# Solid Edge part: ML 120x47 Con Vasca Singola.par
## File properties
Title: ML 120 x 47 VASCA CENTRALE
Author: DESYS
Template: Iso Part.par
Last saved by: i.fialdini
Revision: 64
Application: Solid Edge
Tipo di contenuto documento: 0
Accuracy: 0.990
Document Number: 3007
Revision: 0
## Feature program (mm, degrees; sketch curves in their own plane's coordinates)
sketch for "unnamed Protrusion 1" plane through (10.8674, 0, 10.8674) normal (0, -1, 0) x-axis (1, 0, 0)
  line (-615.8674, 149.1326) -> (594.1326, 149.1326)
  line (594.1326, 149.1326) -> (594.1326, 94.1326)
  line (594.1326, 94.1326) -> (544.1326, 94.1326)
  arc centre (463.3203, 133.7479) radius 90 from (471.6326, 44.1326) to (544.1326, 94.1326) ccw
  line (454.1326, -10.8674) -> (471.6326, 44.1326)
  line (454.1326, -10.8674) -> (-475.8674, -10.8674)
  line (-475.8674, -10.8674) -> (-493.3674, 44.1326)
  arc centre (-485.0551, 133.7479) radius 90 from (-493.3674, 44.1326) to (-565.8674, 94.1326) cw
  line (-615.8674, 94.1326) -> (-565.8674, 94.1326)
  line (-615.8674, 149.1326) -> (-615.8674, 94.1326)
  dimension (linear) = 615.8674
  dimension (linear) = 615.8674
  dimension (linear) = 594.1326
  dimension (linear) = 454.1326
  dimension (linear) = 594.1326
  dimension (linear) = 615.8674
extrude "unnamed Protrusion 1" add finite 465 along +normal
sketch for "ScavoEstrusione_2" plane through (480, -232.5, 160) normal (0, 0, 1) x-axis (1, 0, 0)
  line (-1065, 212.5) -> (105, 212.5)
  line (105, 212.5) -> (105, -212.0497)
  line (105, -212.0497) -> (-1065, -212.0497)
  line (-1065, -212.0497) -> (-1065, 212.5)
  dimension (linear) = 105
  dimension (linear) = 1065
extrude "ScavoEstrusione_2" cut finite 12 along -normal
sketch for "ScavoEstrusione_12" plane through (0, -232.2749, 148) normal (0, 0, 1) x-axis (1, 0, 0)
  line (-315, -212.2749) -> (315, -212.2749)
  line (315, -212.2749) -> (315, 92.2749)
  line (315, 92.2749) -> (-315, 92.2749)
  line (-315, 92.2749) -> (-315, -212.2749)
  dimension (linear) = 315
extrude "ScavoEstrusione_12" cut finite 115 along -normal
fillet "Rotondo_1" radius 300
draft "Spoglia_8"  Angles1 = 5 deg
sketch for "unnamed Protrusion 2" plane through (0, 0, 0) normal (1, 0, 0) x-axis (0, 1, 0)
  line (-444.5497, 148) -> (-275, 33)
extrude "unnamed Protrusion 2" add through
sketch for "unnamed Cutout 1" plane through (0, 0, 0) normal (1, 0, 0) x-axis (0, 1, 0)
  line (-465, 105) -> (-410, 105)
  line (-410, 105) -> (-335, 55)
  line (-335, 55) -> (-330, 0)
extrude "unnamed Cutout 1" cut through
sketch for "ScavoEstrusione_10" plane through (0, 0, 80) normal (0, 1, 0) x-axis (-1, 0, 0)
  line (498.4091, 25) -> (610, 25)
  line (465.6895, -77.833) -> (498.4091, 25)
extrude "ScavoEstrusione_10" cut finite 20 along -normal
mirror "unnamed Mirror 1" of "ScavoEstrusione_10" about plane through (0, 0, 0) normal (1, 0, 0)
extrude "unnamed Cutout 2" cut finite 20
thinwall "Spessoramento_1"  Thickness = 25 mm
sketch for "unnamed Protrusion 3" plane through (0, -25, 61.5) normal (0, -1, 0) x-axis (-1, 0, 0)
  line (465, 61.5) -> (430, 61.5)
  line (430, 61.5) -> (430, -3.3526)
  dimension (linear) = 465
extrude "unnamed Protrusion 3" add through along +normal
mirror "unnamed Mirror 2" of "unnamed Protrusion 3" about plane through (0, 0, 0) normal (1, 0, 0)
extrude "unnamed Protrusion 4" add through
sketch for "unnamed Protrusion 5" plane through (-430, -208.4653, 61.5) normal (1, 0, 0) x-axis (0, -1, 0)
  line (121.5347, 61.5) -> (91.5347, 61.5)
  line (91.5347, 61.5) -> (91.5347, 18.4226)
  dimension (linear) = 121.5347
extrude "unnamed Protrusion 5" add through along +normal
replace surface "unnamed ReplaceSurface 1"
sketch for "ProtrusioneEstrusa_7" plane through (0, -160, 23) normal (0, 0, -1) x-axis (1, 0, 0)
  line (-216.875, 140) -> (-326.875, 140)
  line (-326.875, 140) -> (-326.875, -32.8471)
  line (78.8327, -32.8471) -> (-326.875, -32.8471)
  dimension (linear) = 216.875
extrude "ProtrusioneEstrusa_7" add through along -normal  Profile_Plane1_Distance = 100 mm
replace surface "unnamed ReplaceSurface 2"
sketch for "unnamed Protrusion 6" plane through (-251.6519, -210.4203, 23) normal (0, 0, -1) x-axis (1, 0, 0)
  line (75.2231, -84.5797) -> (39.7769, -185.4203)
  line (-75.2231, -185.4203) -> (39.7769, -185.4203)
  line (-75.2231, -84.5797) -> (-75.2231, -185.4203)
  dimension (linear) = 75.2231
extrude "unnamed Protrusion 6" add through along -normal
mirror "unnamed Mirror 3" of "unnamed Protrusion 6" about plane through (0, 0, 0) normal (1, 0, 0)
extrude "unnamed Protrusion 7" add through
sketch for "ProtrusioneEstrusa_12" plane through (0, -211.0765, 8) normal (0, 0, -1) x-axis (1, 0, 0)
  circle centre (0, 0.9235) radius 32.5
extrude "ProtrusioneEstrusa_12" add finite 35 along +normal
sketch for "ScavoEstrusione_13" plane through (-5.7631, -212.5, -27) normal (0, 0, -1) x-axis (1, 0, 0)
  circle centre (5.7631, -0.5) radius 27.5
extrude "ScavoEstrusione_13" cut finite 385 along -normal
sketch for "unnamed Protrusion 8" plane through (0, 0, 0) normal (1, 0, 0) x-axis (0, 1, 0)
  line (-179.5, -20.3567) -> (-90, -20.3567)
  line (-90, -20.3567) -> (-90, 105)
extrude "unnamed Protrusion 8" add finite 50 symmetric
sketch for "ProtrusioneEstrusa_17" plane through (0, -90, 51.3216) normal (0, 1, 0) x-axis (1, 0, 0)
  arc centre (25, -92.5404) radius 65.862 from (25, -26.6784) to (87.4706, -71.6784) cw
  line (25, -71.6784) -> (87.4706, -71.6784)
  line (25, -26.6784) -> (25, -71.6784)
  dimension (linear) = 25
extrude "ProtrusioneEstrusa_17" add finite 35 along -normal
fillet "unnamed Round 1"
fillet "Rotondo_12" radius 10
fillet "Rotondo_13" radius 10
fillet "Rotondo_15" radius 10
fillet "Rotondo_16" radius 10
fillet "Rotondo_17" radius 2
fillet "Rotondo_18" radius 5
fillet "Rotondo_19" radius 5
fillet "Rotondo_20" radius 20
fillet "Rotondo_21" radius 20
fillet "Rotondo_22" radius 20
sketch for "ScavoEstrusione_16" #1 plane through (0, 0, 77.5) normal (0, 1, 0) x-axis (1, 0, 0)
  line (372.5, -15.7372) -> (372.5, -10.7372)
  arc centre (362.5, -10.7372) radius 10 from (362.5, -0.7372) to (372.5, -10.7372) cw
  line (347.5, -0.7372) -> (362.5, -0.7372)
  arc centre (347.5, -10.7372) radius 10 from (347.5, -0.7372) to (337.5, -10.7372) ccw
  line (337.5, -15.7372) -> (337.5, -10.7372)
  arc centre (347.5, -15.7372) radius 10 from (347.5, -25.7372) to (337.5, -15.7372) cw
  line (347.5, -25.7372) -> (362.5, -25.7372)
  arc centre (362.5, -15.7372) radius 10 from (362.5, -25.7372) to (372.5, -15.7372) ccw
sketch for "ScavoEstrusione_16" #2 plane through (0, 0, 77.5) normal (0, 1, 0) x-axis (1, 0, 0)
  line (-372.5, -16.3838) -> (-372.5, -11.3838)
  arc centre (-362.5, -11.3838) radius 10 from (-362.5, -1.3838) to (-372.5, -11.3838) ccw
  line (-347.5, -1.3838) -> (-362.5, -1.3838)
  arc centre (-347.5, -11.3838) radius 10 from (-347.5, -1.3838) to (-337.5, -11.3838) cw
  line (-337.5, -16.3838) -> (-337.5, -11.3838)
  arc centre (-347.5, -16.3838) radius 10 from (-347.5, -26.3838) to (-337.5, -16.3838) ccw
  line (-347.5, -26.3838) -> (-362.5, -26.3838)
  arc centre (-362.5, -16.3838) radius 10 from (-362.5, -26.3838) to (-372.5, -16.3838) cw
  dimension (linear) = 337.5
extrude "ScavoEstrusione_16" cut finite 105 along -normal
fillet "Rotondo_25" radius 3
fillet "Rotondo_26" radius 8
sketch for "ScavoEstrusione_17" plane through (0, -73.1662, 123) normal (0, 0, -1) x-axis (-1, 0, 0)
  circle centre (0, 7.7793) radius 18
extrude "ScavoEstrusione_17" cut finite 490 along -normal
fillet "Rotondo_27" radius 5
fillet "Rotondo_28" radius 5
fillet "Rotondo_29" radius 5
sketch for "ScavoEstrusione_18" plane through (0, 0, 77.5) normal (0, 1, 0) x-axis (1, 0, 0)
extrude "ScavoEstrusione_18" cut finite 70 symmetric
fillet "Rotondo_31" radius 3
fillet "Rotondo_33" radius 4
fillet "Rotondo_34" radius 3
fillet "Rotondo_36" radius 2
fillet "Rotondo_37" radius 1
fillet "Rotondo_38" radius 3
fillet "Rotondo_40" radius 2
fillet "Rotondo_43" radius 10
fillet "Rotondo_44" radius 3
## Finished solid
Body 1: solid body, 344 faces, 771 edges, 425 vertices.
  Faces by surface: cylinder 143, blend 67, torus 58, plane 57, sphere 19
  Edges by curve: circle 341, line 285, intersection 83, ellipse 62
Bounding box of the edges (mm; curved faces can reach further): 1210.000 x 465.000 x 187.000, from (-605, -465, -27) to (605, 0, 160).
Cylindrical faces by radius (mm): R2 x4, R3 x37, R4 x16, R5 x18, R5.812 x2, R10 x22, R18 x1, R20 x31, R27.5 x1, R32.5 x1, R40 x1, R50 x2, R65.862 x1, R90 x2, R300 x2, R325 x2
Toroidal faces (ring radius, tube radius in mm): R2.812 r3 x4, R6 r4 x4, R12 r2 x2, R13 r3 x16, R15 r5 x1, R17 r3 x4, R23 r3 x4, R23 r5 x3, R25 r5 x2, R29.5 r2 x1, R31.5 r1 x1, R35.5 r8 x1, R37 r3 x2, R37.5 r5 x2, R40 r20 x4, R53 r3 x4, R62.862 r3 x1, R85 r5 x2
Spherical faces by radius (mm): R4 x1, R5 x6, R10 x4, R20 x8
Planar faces by outward normal: +x 8, +y 7, +z 5, -x 8, -y 5, -z 14, oblique 10
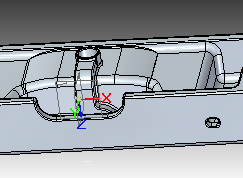
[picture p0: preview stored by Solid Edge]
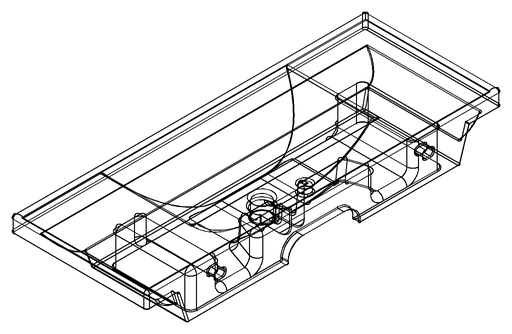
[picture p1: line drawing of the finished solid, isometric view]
